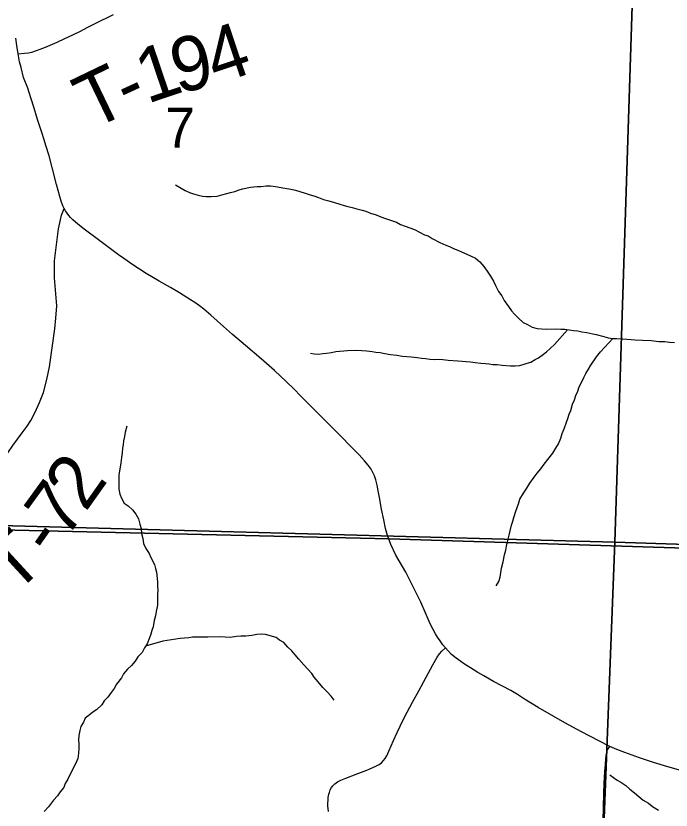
# Model space of a CAD drawing. Extents: x -3.3 to 34, y 0 to 56.8.
# Drawn here: x 0.148 to 0.833, y 33.346 to 34.177 of the extents above; entities that cross this region are included whole.
import ezdxf

# ---------------------------------------------------------------- set-up
doc = ezdxf.new("R2010")
doc.units = 0
for name, color, linetype in [('GM_X_Corporation', 7, 'Continuous'), ('GM_X_County_Road', 7, 'Continuous'), ('GM_X_Section_Text', 7, 'Continuous'), ('GM_X_Township_Road', 7, 'Continuous'), ('GM_X_Township_Road_Text', 7, 'Continuous'), ('GT_Project_Soil_Layers', 7, 'Continuous')]:
    doc.layers.add(name, color=color, linetype=linetype)

msp = doc.modelspace()

# ---------------------------------------------------------------- linework, layer by layer
at = {"layer": 'GM_X_Corporation'}
for points in [[(1.84017, 34.87705), (-3.30393, 34.87705), (-3.30393, 33.7379), (-1.95594, 33.69761), (-1.4178, 33.68276), (-1.31578, 33.67985), (-1.26472, 33.67853), (-1.26192, 33.67846), (-1.25588, 33.6783), (-1.24768, 33.67809), (-0.68402, 33.66353), (0.07113, 33.6404), (0.53861, 33.62974), (1.16908, 33.60969), (1.26798, 33.60697), (1.38132, 33.6045), (1.39386, 33.60423), (1.40335, 33.60404), (1.51565, 33.60182), (1.54523, 33.60124), (1.79797, 33.59224), (1.81648, 34.17132), (1.8337, 34.72257), (1.83943, 34.85654)], [(0.80707, 34.64081), (0.77432, 33.62613), (-0.25432, 33.65409), (-0.21861, 34.67261)], [(0.80707, 34.64081), (1.83091, 34.60519), (1.82548, 34.44632), (1.79698, 33.59314), (0.77432, 33.62613)], [(-0.25432, 33.65409), (0.77432, 33.62613), (0.73569, 32.62424), (-0.28775, 32.6826)], [(1.79698, 33.59314), (1.79067, 33.44183), (1.75705, 32.57759), (0.73569, 32.62424), (0.77432, 33.62613)]]:
    msp.add_lwpolyline(points, close=True, dxfattribs=at)
msp.add_lwpolyline([(1.69805, 31.56614), (1.74587, 32.36303), (1.74609, 32.36849), (1.74848, 32.4264), (1.74928, 32.44591), (1.75537, 32.59405), (1.75808, 32.65987), (1.75838, 32.6672), (1.7602, 32.71145), (1.78315, 33.26936), (1.79014, 33.43939), (1.79797, 33.59224), (1.54523, 33.60124), (1.51565, 33.60182), (1.40335, 33.60404), (1.39386, 33.60423), (1.38132, 33.6045), (1.26798, 33.60697), (1.16908, 33.60969), (0.53861, 33.62974), (0.07113, 33.6404), (-0.68402, 33.66353)], dxfattribs=at)
at = {"layer": 'GM_X_County_Road'}
for points in [[(0.5368, 33.63319), (0.53477, 33.64053), (0.53278, 33.64946), (0.53057, 33.6606), (0.52831, 33.67294), (0.52705, 33.67979), (0.52583, 33.68574), (0.52442, 33.69136), (0.52302, 33.69539), (0.52137, 33.69909), (0.51949, 33.70246), (0.51653, 33.70682), (0.51282, 33.71117), (0.50691, 33.7175), (0.49778, 33.72695), (0.48856, 33.73623), (0.47978, 33.74504), (0.47179, 33.75308), (0.46252, 33.76239), (0.45387, 33.77108), (0.44575, 33.77924), (0.43893, 33.78613), (0.43079, 33.79436), (0.41846, 33.8057), (0.40465, 33.81779), (0.38813, 33.83184), (0.37466, 33.84352), (0.36519, 33.85174), (0.35188, 33.86366), (0.34456, 33.8699), (0.33995, 33.87336), (0.33511, 33.87689), (0.33083, 33.87977), (0.32681, 33.88224), (0.31932, 33.88684), (0.30962, 33.89241), (0.29787, 33.89917), (0.28438, 33.90722), (0.27041, 33.91635), (0.26083, 33.92278), (0.25545, 33.92687), (0.24552, 33.93404), (0.23449, 33.94233), (0.21954, 33.95359), (0.21287, 33.95884), (0.20771, 33.96339), (0.20531, 33.96567), (0.20353, 33.96786), (0.19988, 33.97271), (0.19837, 33.97533), (0.19709, 33.97792), (0.19528, 33.98293), (0.19388, 33.98786), (0.19041, 34.00036), (0.18619, 34.01676), (0.1827, 34.03028), (0.1795, 34.04113), (0.17755, 34.04705), (0.17506, 34.05461), (0.1708, 34.06821), (0.16708, 34.08012), (0.16368, 34.09102), (0.16059, 34.10089), (0.15602, 34.11202), (0.15344, 34.12259), (0.15188, 34.12868), (0.15114, 34.13262), (0.15048, 34.13698), (0.14907, 34.14558), (0.14792, 34.15324)], [(0.8434, 33.38725), (0.82992, 33.39128), (0.81504, 33.3958), (0.80033, 33.40057), (0.78487, 33.406), (0.77665, 33.40929), (0.76917, 33.41257), (0.75774, 33.41841), (0.73949, 33.42786), (0.72223, 33.43732), (0.71056, 33.44397), (0.69445, 33.45335), (0.68007, 33.46206), (0.67259, 33.46682), (0.66568, 33.47085), (0.64767, 33.48055), (0.63756, 33.48622), (0.63107, 33.49001), (0.62343, 33.49469), (0.61726, 33.49864), (0.61323, 33.50143), (0.60855, 33.50496), (0.60378, 33.50875), (0.60008, 33.51253), (0.59721, 33.51565), (0.59466, 33.51894), (0.59178, 33.5228), (0.58915, 33.52683), (0.58701, 33.53028), (0.58438, 33.53489), (0.58241, 33.53883), (0.58044, 33.54303), (0.57616, 33.55281), (0.57156, 33.5635), (0.56613, 33.57451), (0.56079, 33.5852), (0.55577, 33.59465), (0.54558, 33.61257), (0.54016, 33.62375), (0.5368, 33.63319)]]:
    msp.add_lwpolyline(points, dxfattribs=at)
at = {"layer": 'GM_X_Township_Road'}
for points in [[(0.15048, 34.13698), (0.15689, 34.13747), (0.16133, 34.13802), (0.16489, 34.13876), (0.16965, 34.14033), (0.17348, 34.14171), (0.17913, 34.144), (0.19111, 34.14918), (0.19927, 34.1529), (0.20776, 34.15689), (0.21556, 34.1607), (0.22262, 34.16437), (0.23106, 34.16869), (0.25022, 34.17803)], [(0.13971, 33.71953), (0.14493, 33.72723), (0.15474, 33.74066), (0.15987, 33.74734), (0.16383, 33.75327), (0.16823, 33.76204), (0.17285, 33.77215), (0.17679, 33.78255), (0.18029, 33.79627), (0.18304, 33.80939), (0.18861, 33.84926), (0.18999, 33.86056), (0.19073, 33.87347), (0.18853, 33.90269), (0.18827, 33.91384), (0.18836, 33.92049), (0.19108, 33.94284), (0.19262, 33.9538), (0.19461, 33.96347), (0.19591, 33.96818), (0.19837, 33.97533)], [(0.47485, 33.34461), (0.47444, 33.35036), (0.47472, 33.35918), (0.47536, 33.36243), (0.4759, 33.36429), (0.47687, 33.36701), (0.47807, 33.36962), (0.47953, 33.37144), (0.48163, 33.37345), (0.4843, 33.3754), (0.48789, 33.37735), (0.49302, 33.3794), (0.50376, 33.38351), (0.51501, 33.38782), (0.52131, 33.39031), (0.52518, 33.39207), (0.52797, 33.39374), (0.53034, 33.3955), (0.53253, 33.39777), (0.53434, 33.39995), (0.53585, 33.4028), (0.53817, 33.40756), (0.54313, 33.41873), (0.54698, 33.427), (0.5499, 33.43359), (0.55454, 33.44314), (0.56299, 33.45869), (0.56948, 33.47062), (0.57709, 33.48495), (0.58424, 33.49804), (0.58853, 33.50572), (0.59104, 33.50923), (0.59358, 33.51201), (0.59721, 33.51565)], [(0.76216, 33.33393), (0.76261, 33.34978), (0.76306, 33.36286), (0.76343, 33.37387), (0.76409, 33.38644), (0.76459, 33.39368), (0.765, 33.3996), (0.76549, 33.40305), (0.76606, 33.40609), (0.76696, 33.40897), (0.76917, 33.41257)]]:
    msp.add_lwpolyline(points, dxfattribs=at)
at = {"layer": 'GT_Project_Soil_Layers'}
for points in [[(0.31501, 34.00005), (0.32075, 33.99634), (0.32495, 33.99412), (0.32954, 33.9919), (0.33373, 33.99044), (0.33868, 33.98899), (0.34324, 33.98792), (0.34704, 33.98759), (0.35234, 33.98767), (0.3584, 33.98813), (0.36332, 33.98934), (0.3686, 33.99093), (0.37238, 33.99174), (0.37692, 33.99294), (0.38145, 33.99453), (0.38522, 33.99572), (0.39354, 33.99735), (0.40035, 33.99821), (0.40452, 33.99827), (0.40983, 33.99872), (0.41437, 33.99878), (0.41969, 33.9981), (0.42919, 33.99633), (0.43566, 33.99528), (0.4406, 33.99421), (0.4505, 33.99132), (0.45583, 33.98949), (0.45964, 33.9884), (0.46459, 33.98657), (0.46992, 33.98475), (0.47525, 33.98331), (0.48134, 33.98149), (0.48668, 33.97967), (0.49125, 33.97821), (0.49505, 33.97713), (0.49962, 33.97605), (0.50456, 33.97498), (0.51027, 33.97354), (0.51407, 33.97246), (0.51903, 33.97025), (0.52475, 33.96843), (0.5297, 33.9666), (0.53466, 33.96477), (0.54075, 33.96258), (0.54608, 33.96075), (0.55028, 33.95853), (0.56019, 33.95487), (0.56477, 33.95304), (0.57546, 33.94749), (0.57927, 33.94641), (0.58347, 33.94381), (0.59149, 33.93974), (0.5976, 33.93679), (0.60141, 33.93532), (0.60561, 33.93348), (0.61018, 33.93165), (0.62353, 33.92576), (0.62887, 33.92317), (0.6331, 33.91943), (0.63734, 33.91456), (0.64082, 33.90967), (0.6443, 33.9044), (0.64741, 33.89913), (0.64974, 33.8946), (0.65286, 33.88819), (0.65634, 33.88368), (0.65868, 33.87878), (0.66331, 33.87277), (0.66641, 33.86825), (0.66949, 33.8645), (0.67372, 33.86038), (0.67871, 33.85589), (0.68329, 33.85368), (0.68787, 33.85109), (0.6932, 33.84964), (0.70269, 33.84901), (0.71217, 33.84915), (0.71786, 33.84885), (0.72203, 33.8489), (0.73115, 33.84751), (0.7357, 33.84719), (0.73989, 33.84611), (0.74521, 33.84543), (0.75129, 33.84399), (0.75509, 33.84329), (0.76309, 33.84112), (0.76765, 33.84004), (0.77221, 33.83935), (0.77638, 33.83903), (0.78246, 33.83873), (0.79156, 33.8381), (0.79574, 33.83777), (0.80333, 33.8375), (0.81243, 33.83725), (0.82041, 33.83622), (0.82686, 33.83593), (0.8318, 33.83524), (0.83673, 33.83493)], [(0.45619, 33.82393), (0.46, 33.82322), (0.46455, 33.82291), (0.4691, 33.82335), (0.47288, 33.82378), (0.47818, 33.82462), (0.48272, 33.82544), (0.4865, 33.82587), (0.49105, 33.82632), (0.49483, 33.82675), (0.50469, 33.82689), (0.51494, 33.82627), (0.52063, 33.82559), (0.52443, 33.82488), (0.52899, 33.82457), (0.53393, 33.8235), (0.54001, 33.82244), (0.54647, 33.82177), (0.55255, 33.82072), (0.56128, 33.82008), (0.56773, 33.81941), (0.57229, 33.81871), (0.57647, 33.81839), (0.58103, 33.8177), (0.58596, 33.81739), (0.58975, 33.81744), (0.59469, 33.81713), (0.6, 33.81644), (0.61025, 33.81583), (0.62353, 33.81487), (0.62847, 33.81418), (0.63417, 33.8135), (0.6391, 33.81319), (0.6429, 33.81286), (0.6467, 33.81216), (0.65125, 33.81184), (0.65657, 33.81116), (0.6653, 33.81052), (0.67023, 33.81058), (0.67477, 33.81103), (0.67855, 33.81184), (0.6827, 33.81342), (0.68648, 33.81461), (0.69099, 33.81733), (0.69476, 33.8189), (0.69851, 33.82161), (0.70302, 33.82509), (0.70676, 33.82856), (0.71125, 33.8328), (0.72511, 33.84843)], [(0.65026, 33.58052), (0.65323, 33.58512), (0.65468, 33.5897), (0.65607, 33.59884), (0.6575, 33.60569), (0.65891, 33.61293), (0.66036, 33.61789), (0.66106, 33.62208), (0.66286, 33.62932), (0.66394, 33.63351), (0.66501, 33.63808), (0.66645, 33.6438), (0.66791, 33.648), (0.66899, 33.65182), (0.6708, 33.65867), (0.67372, 33.66631), (0.67517, 33.67127), (0.67888, 33.6774), (0.6826, 33.68277), (0.68556, 33.68775), (0.69002, 33.69427), (0.69338, 33.69849), (0.69711, 33.70272), (0.70046, 33.7077), (0.70456, 33.7127), (0.70978, 33.71923), (0.71274, 33.72459), (0.71571, 33.72918), (0.7179, 33.73491), (0.71935, 33.73987), (0.72156, 33.74484), (0.72374, 33.75171), (0.7252, 33.75552), (0.72666, 33.7601), (0.7285, 33.76392), (0.73031, 33.7704), (0.73214, 33.77499), (0.73359, 33.77957), (0.73581, 33.78415), (0.73726, 33.78873), (0.7391, 33.79256), (0.74206, 33.79829), (0.74428, 33.8025), (0.74687, 33.80709), (0.74947, 33.81131), (0.75541, 33.82013), (0.75951, 33.82512), (0.77248, 33.83933)], [(0.26425, 33.74757), (0.26244, 33.74109), (0.26174, 33.73652), (0.26066, 33.73233), (0.26034, 33.72814), (0.25964, 33.72434), (0.25932, 33.71978), (0.25863, 33.71483), (0.25795, 33.70912), (0.25585, 33.69618), (0.25556, 33.6901), (0.25567, 33.68175), (0.25688, 33.67645), (0.25845, 33.67229), (0.26118, 33.66701), (0.26539, 33.66403), (0.27, 33.65992), (0.27348, 33.65541), (0.27619, 33.65051), (0.27779, 33.64483), (0.27899, 33.64029), (0.27944, 33.63536), (0.28065, 33.63006), (0.28148, 33.62476), (0.28383, 33.61947), (0.28731, 33.6142), (0.28926, 33.61005), (0.29316, 33.60289), (0.29397, 33.59872), (0.29516, 33.59494), (0.29606, 33.5847), (0.29612, 33.58014), (0.29656, 33.57559), (0.29624, 33.57179), (0.29629, 33.56761), (0.29601, 33.56039), (0.29459, 33.55353), (0.2939, 33.54896), (0.29282, 33.54439), (0.29178, 33.53754), (0.29031, 33.53372), (0.28923, 33.52991), (0.28776, 33.52609), (0.28519, 33.51997), (0.2826, 33.51576), (0.28001, 33.51078), (0.27553, 33.50616), (0.27294, 33.50157), (0.26882, 33.49733), (0.26471, 33.49348), (0.2606, 33.48848), (0.25839, 33.48427), (0.25317, 33.47774), (0.25096, 33.47315), (0.2476, 33.46893), (0.24426, 33.46394), (0.24052, 33.46009), (0.23792, 33.45588), (0.2323, 33.45086), (0.22855, 33.44853), (0.2248, 33.44506), (0.22067, 33.44196), (0.21884, 33.43775), (0.21586, 33.43353), (0.21478, 33.42934), (0.21372, 33.42401), (0.2134, 33.41945), (0.21384, 33.41489), (0.21391, 33.41034), (0.21359, 33.40539), (0.21291, 33.40007), (0.2107, 33.3951), (0.20848, 33.39127), (0.20221, 33.37826), (0.19962, 33.37367), (0.19817, 33.36947), (0.19444, 33.36486), (0.19146, 33.36102), (0.18735, 33.3564), (0.18214, 33.34949), (0.17766, 33.34449)], [(0.48091, 33.46079), (0.47781, 33.46492), (0.47358, 33.4698), (0.46896, 33.4743), (0.46434, 33.47993), (0.4601, 33.48481), (0.45739, 33.48895), (0.45353, 33.49345), (0.4493, 33.49795), (0.44391, 33.50396), (0.44005, 33.50846), (0.43658, 33.51259), (0.43236, 33.51633), (0.42812, 33.52121), (0.42392, 33.52381), (0.42009, 33.52642), (0.40905, 33.52968), (0.40525, 33.53001), (0.39995, 33.52955), (0.39466, 33.52872), (0.3886, 33.52788), (0.38329, 33.5278), (0.37875, 33.52736), (0.37231, 33.52651), (0.367, 33.52681), (0.36245, 33.52713), (0.3488, 33.52694), (0.33288, 33.52672), (0.32909, 33.52628), (0.32, 33.5254), (0.30184, 33.52249), (0.28359, 33.51737)], [(0.76939, 33.38274), (0.77322, 33.38014), (0.77706, 33.37715), (0.78087, 33.3753), (0.78585, 33.37157), (0.79008, 33.36783), (0.79506, 33.3641), (0.79966, 33.35999), (0.80427, 33.35625), (0.80962, 33.35329), (0.81384, 33.34955), (0.81996, 33.34583)]]:
    msp.add_lwpolyline(points, dxfattribs=at)

# ---------------------------------------------------------------- texts
at = {"layer": 'GM_X_Section_Text'}
msp.add_text('7', height=0.04186, rotation=0.00001, dxfattribs=at).set_placement((0.3041, 34.03879))
at = {"layer": 'GM_X_Township_Road_Text'}
for s, rotation, p in [('4', 18.56896, (0.35749, 34.10445)), ('9', 12.30302, (0.31677, 34.09519)), ('1', 18.65545, (0.28522, 34.08444)), ('T', 25.72554, (0.22745, 34.05693)), ('-', 24.73207, (0.2655, 34.07526)), ('2', 54.64389, (0.22076, 33.65686)), ('7', 54.02313, (0.19981, 33.62799)), ('T', 42.58415, (0.14647, 33.57042)), ('-', 54.81337, (0.18648, 33.60909))]:
    msp.add_text(s, height=0.05682, rotation=rotation, dxfattribs=at).set_placement(p)

doc.saveas('drawing.dxf')
